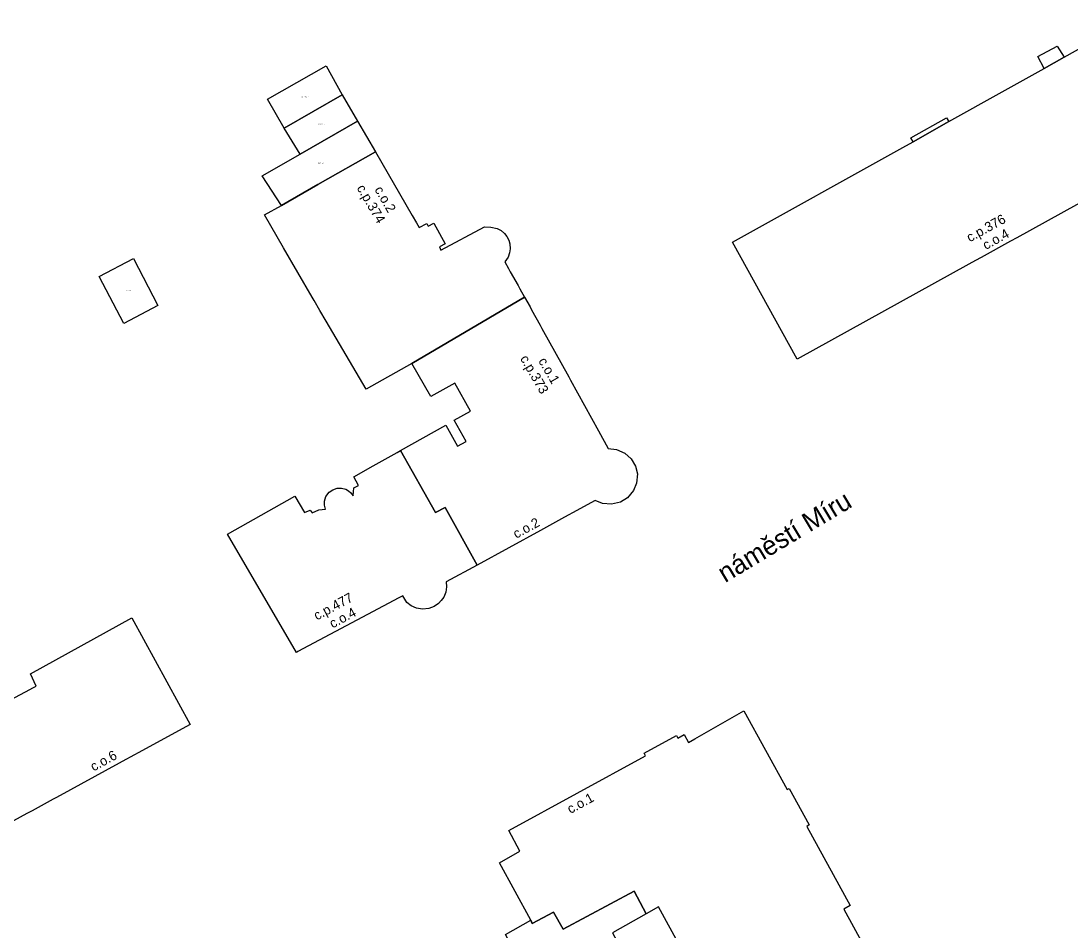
# Model space of a CAD drawing. Extents: x -600391 to -599491, y -1160176 to -1159402.
# Drawn here: x -600144.5 to -600035.1, y -1159820.9 to -1159726.1 of the extents above; entities that cross this region are included whole.
import ezdxf

# ---------------------------------------------------------------- set-up
doc = ezdxf.new("R2010")
doc.units = 0
for name, color, linetype in [('Level 10', 7, 'Continuous'), ('Level 11', 7, 'Continuous'), ('Level 12', 7, 'Continuous'), ('Level 24', 7, 'Continuous'), ('Level 25', 7, 'Continuous'), ('Level 61', 7, 'Continuous'), ('Level 62', 7, 'Continuous')]:
    doc.layers.add(name, color=color, linetype=linetype)

msp = doc.modelspace()

# ---------------------------------------------------------------- linework, layer by layer
at = {"layer": 'Level 61'}
for points in [[(-600035.83, -1159729.89), (-600029.11, -1159726.12)], [(-600038.55, -1159729.81), (-600036.54, -1159728.74)], [(-600036.54, -1159728.74), (-600035.83, -1159729.89)], [(-600037.91, -1159731.05), (-600038.55, -1159729.81)], [(-600035.83, -1159729.89), (-600037.91, -1159731.05)], [(-600037.91, -1159731.05), (-600035.83, -1159729.89)], [(-600118.8, -1159734.26), (-600112.68, -1159730.8)], [(-600112.68, -1159730.8), (-600111.01, -1159733.8)], [(-600042.29, -1159733.51), (-600037.91, -1159731.05)], [(-600117.04, -1159737.28), (-600118.8, -1159734.26)], [(-600111.01, -1159733.8), (-600117.04, -1159737.28)], [(-600117.04, -1159737.28), (-600111.01, -1159733.8)], [(-600111.01, -1159733.8), (-600109.42, -1159736.56)], [(-600047.82, -1159736.59), (-600042.29, -1159733.51)], [(-600051.77, -1159738.28), (-600048.07, -1159736.2)], [(-600048.07, -1159736.2), (-600047.82, -1159736.59)], [(-600115.4, -1159739.99), (-600117.04, -1159737.28)], [(-600115.4, -1159739.99), (-600109.42, -1159736.56)], [(-600109.42, -1159736.56), (-600115.4, -1159739.99)], [(-600109.42, -1159736.56), (-600107.55, -1159739.76)], [(-600047.82, -1159736.59), (-600051.53, -1159738.69)], [(-600051.53, -1159738.69), (-600047.82, -1159736.59)], [(-600052.61, -1159739.29), (-600051.53, -1159738.69)], [(-600051.53, -1159738.69), (-600051.77, -1159738.28)], [(-600022.11, -1159738.38), (-600040.75, -1159748.71)], [(-600113.55, -1159743.15), (-600107.55, -1159739.76)], [(-600107.55, -1159739.76), (-600113.55, -1159743.15)], [(-600107.55, -1159739.76), (-600103.72, -1159746.38)], [(-600070.35, -1159749.14), (-600052.61, -1159739.29)], [(-600119.33, -1159742.25), (-600115.4, -1159739.99)], [(-600117.35, -1159745.33), (-600119.33, -1159742.25)], [(-600117.35, -1159745.33), (-600113.55, -1159743.15)], [(-600113.55, -1159743.15), (-600117.35, -1159745.33)], [(-600119.11, -1159746.31), (-600117.35, -1159745.33)], [(-600117.14, -1159749.73), (-600119.11, -1159746.31)], [(-600103.72, -1159746.38), (-600103.73, -1159746.38)], [(-600103.73, -1159746.38), (-600103.28, -1159747.14)], [(-600103.28, -1159747.14), (-600102.99, -1159747.64)], [(-600102.99, -1159747.64), (-600102.21, -1159747.22)], [(-600102.21, -1159747.22), (-600102.05, -1159747.48)], [(-600102.05, -1159747.48), (-600101.47, -1159747.19)], [(-600101.47, -1159747.19), (-600100.27, -1159749.31)], [(-600100.73, -1159749.99), (-600096.19, -1159747.56)], [(-600096.19, -1159747.56), (-600095.53, -1159747.59)], [(-600095.53, -1159747.59), (-600094.88, -1159747.72)], [(-600094.88, -1159747.72), (-600094.47, -1159747.94)], [(-600094.47, -1159747.94), (-600094.11, -1159748.24)], [(-600094.11, -1159748.24), (-600093.87, -1159748.55)], [(-600093.87, -1159748.55), (-600093.66, -1159748.94)], [(-600100.27, -1159749.31), (-600100.89, -1159749.64)], [(-600100.89, -1159749.64), (-600100.73, -1159749.99)], [(-600093.66, -1159748.94), (-600093.54, -1159749.34)], [(-600093.54, -1159749.34), (-600093.52, -1159749.84)], [(-600063.64, -1159761.34), (-600070.35, -1159749.14)], [(-600041.39, -1159749.06), (-600044.45, -1159750.75)], [(-600040.75, -1159748.71), (-600041.39, -1159749.06)], [(-600114.14, -1159754.88), (-600117.14, -1159749.73)], [(-600093.74, -1159750.73), (-600094.08, -1159751.21)], [(-600093.57, -1159750.27), (-600093.74, -1159750.73)], [(-600093.52, -1159749.84), (-600093.57, -1159750.27)], [(-600044.45, -1159750.75), (-600045.04, -1159751.07)], [(-600136.31, -1159752.74), (-600132.76, -1159750.87)], [(-600132.76, -1159750.87), (-600130.2, -1159755.74)], [(-600094.08, -1159751.21), (-600093.7, -1159751.88)], [(-600045.74, -1159751.46), (-600063.64, -1159761.34)], [(-600045.04, -1159751.07), (-600045.74, -1159751.46)], [(-600133.75, -1159757.61), (-600136.31, -1159752.74)], [(-600093.7, -1159751.88), (-600093.5, -1159752.24)], [(-600093.5, -1159752.24), (-600092.7, -1159753.66)], [(-600092.7, -1159753.66), (-600092.5, -1159754.02)], [(-600092.5, -1159754.02), (-600092.01, -1159754.89)], [(-600113.94, -1159755.23), (-600114.14, -1159754.88)], [(-600103.75, -1159761.78), (-600092.01, -1159754.89)], [(-600092.01, -1159754.89), (-600103.75, -1159761.78)], [(-600092.01, -1159754.89), (-600091.45, -1159755.89)], [(-600130.2, -1159755.74), (-600133.75, -1159757.61)], [(-600113.33, -1159756.26), (-600113.94, -1159755.23)], [(-600091.45, -1159755.89), (-600091.28, -1159756.21)], [(-600091.28, -1159756.21), (-600090.39, -1159757.81)], [(-600112.67, -1159757.39), (-600113.33, -1159756.26)], [(-600108.53, -1159764.45), (-600112.67, -1159757.39)], [(-600090.39, -1159757.81), (-600090.22, -1159758.13)], [(-600090.22, -1159758.13), (-600087.41, -1159763.19)], [(-600103.75, -1159761.78), (-600108.53, -1159764.45)], [(-600101.78, -1159765.24), (-600103.75, -1159761.78)], [(-600099.27, -1159763.84), (-600101.78, -1159765.24)], [(-600097.66, -1159766.74), (-600099.27, -1159763.84)], [(-600087.41, -1159763.19), (-600087.23, -1159763.51)], [(-600087.23, -1159763.51), (-600084.3, -1159768.79)], [(-600099.36, -1159767.69), (-600097.66, -1159766.74)], [(-600104.93, -1159770.86), (-600100.22, -1159768.22)], [(-600100.22, -1159768.22), (-600099, -1159770.4)], [(-600098.11, -1159769.92), (-600099.36, -1159767.69)], [(-600084.3, -1159768.79), (-600083.31, -1159770.65)], [(-600099, -1159770.4), (-600098.11, -1159769.92)], [(-600107.78, -1159772.46), (-600105.3, -1159771.07)], [(-600105.3, -1159771.07), (-600104.93, -1159770.86)], [(-600101.3, -1159777.32), (-600104.93, -1159770.86)], [(-600104.93, -1159770.86), (-600101.3, -1159777.32)], [(-600083.31, -1159770.65), (-600082.43, -1159770.75)], [(-600082.43, -1159770.75), (-600081.59, -1159771.11)], [(-600081.59, -1159771.11), (-600080.91, -1159771.73)], [(-600109.79, -1159773.59), (-600107.78, -1159772.46)], [(-600080.91, -1159771.73), (-600080.46, -1159772.49)], [(-600080.46, -1159772.49), (-600080.27, -1159773.28)], [(-600109.32, -1159774.48), (-600109.79, -1159773.59)], [(-600080.27, -1159773.28), (-600080.35, -1159774.26)], [(-600111.99, -1159774.93), (-600111.52, -1159774.78)], [(-600111.52, -1159774.78), (-600111.07, -1159774.77)], [(-600111.07, -1159774.77), (-600110.65, -1159774.89)], [(-600109.88, -1159775.58), (-600109.79, -1159774.73)], [(-600109.79, -1159774.73), (-600109.32, -1159774.48)], [(-600080.35, -1159774.26), (-600080.68, -1159775.03)], [(-600122.96, -1159779.58), (-600115.94, -1159775.62)], [(-600115.94, -1159775.62), (-600114.95, -1159777.32)], [(-600112.86, -1159776.12), (-600112.7, -1159775.64)], [(-600112.7, -1159775.64), (-600112.37, -1159775.19)], [(-600112.37, -1159775.19), (-600111.99, -1159774.93)], [(-600110.65, -1159774.89), (-600110.36, -1159775.05)], [(-600110.36, -1159775.05), (-600110.1, -1159775.27)], [(-600110.1, -1159775.27), (-600109.88, -1159775.58)], [(-600081.3, -1159775.78), (-600082.03, -1159776.22)], [(-600080.68, -1159775.03), (-600081.3, -1159775.78)], [(-600113.43, -1159777.02), (-600112.76, -1159776.95)], [(-600112.87, -1159776.55), (-600112.86, -1159776.12)], [(-600112.76, -1159776.95), (-600112.87, -1159776.55)], [(-600100.29, -1159776.8), (-600101.3, -1159777.32)], [(-600101.3, -1159777.32), (-600100.29, -1159776.8)], [(-600096.97, -1159782.79), (-600100.29, -1159776.8)], [(-600100.29, -1159776.8), (-600096.97, -1159782.79)], [(-600086.26, -1159776.92), (-600086.59, -1159777.1)], [(-600084.65, -1159776.05), (-600086.26, -1159776.92)], [(-600083.89, -1159776.37), (-600084.65, -1159776.05)], [(-600082.95, -1159776.45), (-600083.89, -1159776.37)], [(-600082.03, -1159776.22), (-600082.95, -1159776.45)], [(-600114.95, -1159777.32), (-600114.36, -1159777.07)], [(-600114.36, -1159777.07), (-600114.14, -1159777.33)], [(-600114.14, -1159777.33), (-600113.43, -1159777.02)], [(-600088.17, -1159777.97), (-600090.37, -1159779.18)], [(-600087.85, -1159777.8), (-600088.17, -1159777.97)], [(-600086.59, -1159777.1), (-600087.85, -1159777.8)], [(-600090.37, -1159779.18), (-600096.97, -1159782.79)], [(-600115.78, -1159791.88), (-600122.96, -1159779.58)], [(-600096.97, -1159782.79), (-600100.19, -1159784.51)], [(-600100.19, -1159784.51), (-600100.15, -1159785.05)], [(-600100.23, -1159785.62), (-600100.44, -1159786.11)], [(-600100.15, -1159785.05), (-600100.23, -1159785.62)], [(-600105.12, -1159786.19), (-600108.36, -1159787.92)], [(-600104.68, -1159785.97), (-600105.12, -1159786.19)], [(-600104.28, -1159786.67), (-600104.68, -1159785.97)], [(-600103.83, -1159787.03), (-600104.28, -1159786.67)], [(-600100.99, -1159786.8), (-600101.45, -1159787.1)], [(-600100.7, -1159786.48), (-600100.99, -1159786.8)], [(-600100.44, -1159786.11), (-600100.7, -1159786.48)], [(-600108.36, -1159787.92), (-600115.62, -1159791.79)], [(-600103.28, -1159787.27), (-600103.83, -1159787.03)], [(-600102.64, -1159787.39), (-600103.28, -1159787.27)], [(-600101.99, -1159787.31), (-600102.64, -1159787.39)], [(-600101.45, -1159787.1), (-600101.99, -1159787.31)], [(-600143.49, -1159794.1), (-600132.93, -1159788.26)], [(-600132.93, -1159788.26), (-600126.86, -1159799.38)], [(-600115.62, -1159791.79), (-600115.78, -1159791.88)], [(-600142.89, -1159795.39), (-600143.49, -1159794.1)], [(-600144.01, -1159795.98), (-600143.17, -1159795.54)], [(-600143.17, -1159795.54), (-600142.89, -1159795.39)], [(-600147.35, -1159797.74), (-600144.01, -1159795.98)], [(-600074.28, -1159800.89), (-600069.17, -1159797.96)], [(-600069.17, -1159797.96), (-600064.67, -1159806.15)], [(-600126.86, -1159799.38), (-600132.26, -1159802.33)], [(-600079.57, -1159802.37), (-600076.21, -1159800.53)], [(-600076.21, -1159800.53), (-600076.04, -1159800.81)], [(-600076.04, -1159800.81), (-600075.4, -1159800.44)], [(-600075.4, -1159800.44), (-600074.93, -1159801.26)], [(-600074.93, -1159801.26), (-600074.28, -1159800.89)], [(-600133.92, -1159803.24), (-600134.24, -1159803.41)], [(-600132.65, -1159802.54), (-600133.92, -1159803.24)], [(-600132.26, -1159802.33), (-600132.65, -1159802.54)], [(-600093.64, -1159810.41), (-600079.43, -1159802.66)], [(-600079.43, -1159802.66), (-600079.57, -1159802.37)], [(-600134.24, -1159803.41), (-600140.76, -1159806.97)], [(-600064.67, -1159806.15), (-600064.47, -1159806.04)], [(-600064.47, -1159806.04), (-600062.36, -1159809.84)], [(-600141.11, -1159807.17), (-600143.3, -1159808.36)], [(-600140.76, -1159806.97), (-600141.11, -1159807.17)], [(-600143.85, -1159808.66), (-600154.94, -1159814.73)], [(-600143.59, -1159808.52), (-600143.85, -1159808.66)], [(-600143.3, -1159808.36), (-600143.59, -1159808.52)], [(-600092.5, -1159812.57), (-600093.64, -1159810.41)], [(-600062.36, -1159809.84), (-600062.62, -1159810)], [(-600062.62, -1159810), (-600058.11, -1159818.23)], [(-600094.64, -1159813.78), (-600092.5, -1159812.57)], [(-600091.37, -1159819.77), (-600094.64, -1159813.78)], [(-600080.6, -1159816.74), (-600087.98, -1159820.71)], [(-600087.98, -1159820.71), (-600080.6, -1159816.74)], [(-600079.35, -1159819.1), (-600080.6, -1159816.74)], [(-600080.6, -1159816.74), (-600079.35, -1159819.1)], [(-600078.08, -1159818.36), (-600079.35, -1159819.1)], [(-600063.12, -1159845.77), (-600078.08, -1159818.36)], [(-600058.11, -1159818.23), (-600058.78, -1159818.63)], [(-600089, -1159818.94), (-600091.21, -1159820.1)], [(-600091.21, -1159820.1), (-600089, -1159818.94)], [(-600087.98, -1159820.71), (-600089, -1159818.94)], [(-600089, -1159818.94), (-600087.98, -1159820.71)], [(-600079.35, -1159819.1), (-600082.86, -1159821.07)], [(-600058.78, -1159818.63), (-600048.7, -1159837.01)], [(-600094.02, -1159821.24), (-600091.37, -1159819.77)], [(-600091.21, -1159820.1), (-600091.37, -1159819.77)], [(-600091.37, -1159819.77), (-600091.21, -1159820.1)]]:
    msp.add_lwpolyline(points, dxfattribs=at)
at = {"layer": 'Level 62'}
for points in [[(-600029.11, -1159726.12), (-600023.56, -1159735.86), (-600022.96, -1159736.85), (-600022.79, -1159737.15), (-600022.11, -1159738.38), (-600040.75, -1159748.71), (-600041.39, -1159749.06), (-600044.45, -1159750.75), (-600045.04, -1159751.07), (-600045.74, -1159751.46), (-600063.64, -1159761.34), (-600070.35, -1159749.14), (-600052.61, -1159739.29), (-600051.53, -1159738.69), (-600047.82, -1159736.59), (-600042.29, -1159733.51), (-600037.91, -1159731.05), (-600035.83, -1159729.89), (-600029.11, -1159726.12)], [(-600038.55, -1159729.81), (-600036.54, -1159728.74), (-600035.83, -1159729.89), (-600037.91, -1159731.05), (-600038.55, -1159729.81)], [(-600111.01, -1159733.8), (-600117.04, -1159737.28), (-600118.8, -1159734.26), (-600112.68, -1159730.8), (-600111.01, -1159733.8)], [(-600111.01, -1159733.8), (-600109.42, -1159736.56), (-600115.4, -1159739.99), (-600117.04, -1159737.28), (-600111.01, -1159733.8)], [(-600047.82, -1159736.59), (-600051.53, -1159738.69), (-600051.77, -1159738.28), (-600048.07, -1159736.2), (-600047.82, -1159736.59)], [(-600117.35, -1159745.33), (-600119.33, -1159742.25), (-600115.4, -1159739.99), (-600109.42, -1159736.56), (-600107.55, -1159739.76), (-600113.55, -1159743.15), (-600117.35, -1159745.33)], [(-600107.55, -1159739.76), (-600103.72, -1159746.38), (-600103.73, -1159746.38), (-600103.28, -1159747.14), (-600102.99, -1159747.64), (-600102.21, -1159747.22), (-600102.05, -1159747.48), (-600101.47, -1159747.19), (-600100.27, -1159749.31), (-600100.89, -1159749.64), (-600100.73, -1159749.99), (-600096.19, -1159747.56), (-600095.53, -1159747.59), (-600094.88, -1159747.72), (-600094.47, -1159747.94), (-600094.11, -1159748.24), (-600093.87, -1159748.55), (-600093.66, -1159748.94), (-600093.54, -1159749.34), (-600093.52, -1159749.84), (-600093.57, -1159750.27), (-600093.74, -1159750.73), (-600094.08, -1159751.21), (-600093.7, -1159751.88), (-600093.5, -1159752.24), (-600092.7, -1159753.66), (-600092.5, -1159754.02), (-600092.01, -1159754.89), (-600103.75, -1159761.78), (-600108.53, -1159764.45), (-600112.67, -1159757.39), (-600113.33, -1159756.26), (-600113.94, -1159755.23), (-600114.14, -1159754.88), (-600117.14, -1159749.73), (-600119.11, -1159746.31), (-600117.35, -1159745.33), (-600113.55, -1159743.15), (-600107.55, -1159739.76)], [(-600136.31, -1159752.74), (-600132.76, -1159750.87), (-600130.2, -1159755.74), (-600133.75, -1159757.61), (-600136.31, -1159752.74)], [(-600086.26, -1159776.92), (-600086.59, -1159777.1), (-600087.85, -1159777.8), (-600088.17, -1159777.97), (-600090.37, -1159779.18), (-600096.97, -1159782.79), (-600100.29, -1159776.8), (-600101.3, -1159777.32), (-600104.93, -1159770.86), (-600100.22, -1159768.22), (-600099, -1159770.4), (-600098.11, -1159769.92), (-600099.36, -1159767.69), (-600097.66, -1159766.74), (-600099.27, -1159763.84), (-600101.78, -1159765.24), (-600103.75, -1159761.78), (-600092.01, -1159754.89), (-600091.45, -1159755.89), (-600091.28, -1159756.21), (-600090.39, -1159757.81), (-600090.22, -1159758.13), (-600087.41, -1159763.19), (-600087.23, -1159763.51), (-600084.3, -1159768.79), (-600083.31, -1159770.65), (-600082.43, -1159770.75), (-600081.59, -1159771.11), (-600080.91, -1159771.73), (-600080.46, -1159772.49), (-600080.27, -1159773.28), (-600080.35, -1159774.26), (-600080.68, -1159775.03), (-600081.3, -1159775.78), (-600082.03, -1159776.22), (-600082.95, -1159776.45), (-600083.89, -1159776.37), (-600084.65, -1159776.05), (-600086.26, -1159776.92)], [(-600104.93, -1159770.86), (-600101.3, -1159777.32), (-600100.29, -1159776.8), (-600096.97, -1159782.79), (-600100.19, -1159784.51), (-600100.15, -1159785.05), (-600100.23, -1159785.62), (-600100.44, -1159786.11), (-600100.7, -1159786.48), (-600100.99, -1159786.8), (-600101.45, -1159787.1), (-600101.99, -1159787.31), (-600102.64, -1159787.39), (-600103.28, -1159787.27), (-600103.83, -1159787.03), (-600104.28, -1159786.67), (-600104.68, -1159785.97), (-600105.12, -1159786.19), (-600108.36, -1159787.92), (-600115.62, -1159791.79), (-600115.78, -1159791.88), (-600122.96, -1159779.58), (-600115.94, -1159775.62), (-600114.95, -1159777.32), (-600114.36, -1159777.07), (-600114.14, -1159777.33), (-600113.43, -1159777.02), (-600112.76, -1159776.95), (-600112.87, -1159776.55), (-600112.86, -1159776.12), (-600112.7, -1159775.64), (-600112.37, -1159775.19), (-600111.99, -1159774.93), (-600111.52, -1159774.78), (-600111.07, -1159774.77), (-600110.65, -1159774.89), (-600110.36, -1159775.05), (-600110.1, -1159775.27), (-600109.88, -1159775.58), (-600109.79, -1159774.73), (-600109.32, -1159774.48), (-600109.79, -1159773.59), (-600107.78, -1159772.46), (-600105.3, -1159771.07), (-600104.93, -1159770.86)], [(-600143.49, -1159794.1), (-600132.93, -1159788.26), (-600126.86, -1159799.38), (-600132.26, -1159802.33), (-600132.65, -1159802.54), (-600133.92, -1159803.24), (-600134.24, -1159803.41), (-600140.76, -1159806.97), (-600141.11, -1159807.17), (-600143.3, -1159808.36), (-600143.59, -1159808.52), (-600143.85, -1159808.66), (-600154.94, -1159814.73), (-600157.7, -1159809.01), (-600156.72, -1159808.45), (-600162.28, -1159796.91), (-600150.75, -1159791.1), (-600147.35, -1159797.74), (-600144.01, -1159795.98), (-600143.17, -1159795.54), (-600142.89, -1159795.39), (-600143.49, -1159794.1)], [(-600091.37, -1159819.77), (-600094.64, -1159813.78), (-600092.5, -1159812.57), (-600093.64, -1159810.41), (-600079.43, -1159802.66), (-600079.57, -1159802.37), (-600076.21, -1159800.53), (-600076.04, -1159800.81), (-600075.4, -1159800.44), (-600074.93, -1159801.26), (-600074.28, -1159800.89), (-600069.17, -1159797.96), (-600064.67, -1159806.15), (-600064.47, -1159806.04), (-600062.36, -1159809.84), (-600062.62, -1159810), (-600058.11, -1159818.23), (-600058.78, -1159818.63), (-600048.7, -1159837.01)], [(-600079.35, -1159819.1), (-600082.86, -1159821.07), (-600080.07, -1159826.22), (-600078.2, -1159829.67), (-600084.15, -1159832.9), (-600086.85, -1159834.36), (-600088.71, -1159830.95), (-600094.02, -1159821.24), (-600091.37, -1159819.77), (-600091.21, -1159820.1), (-600089, -1159818.94), (-600087.98, -1159820.71), (-600080.6, -1159816.74), (-600079.35, -1159819.1)], [(-600063.12, -1159845.77), (-600078.08, -1159818.36), (-600079.35, -1159819.1), (-600080.6, -1159816.74), (-600087.98, -1159820.71), (-600089, -1159818.94), (-600091.21, -1159820.1), (-600091.37, -1159819.77)]]:
    msp.add_lwpolyline(points, dxfattribs=at)

# ---------------------------------------------------------------- texts
at = {"layer": 'Level 10'}
for s, rotation, p in [('c.o.2', 300.1855, (-600107.68, -1159743.68)), ('c.o.4', 28.9333, (-600043.97, -1159749.98)), ('c.o.1', 300.1649, (-600090.62, -1159761.52)), ('c.o.2', 28.7101, (-600092.88, -1159780.05)), ('c.o.4', 28.1335, (-600112.01, -1159789.39)), ('c.o.6', 28.8537, (-600136.9, -1159804.29)), ('c.o.1', 28.6077, (-600087.24, -1159808.71))]:
    msp.add_text(s, height=1, rotation=rotation, dxfattribs=at).set_placement(p)
at = {"layer": 'Level 11'}
msp.add_text('náměstí Míru', height=2, rotation=30.9418, dxfattribs=at).set_placement((-600071.14, -1159784.67))
at = {"layer": 'Level 12'}
for s, rotation, p in [('c.p.374', 300.1855, (-600109.53, -1159743.51)), ('c.p.376', 28.9333, (-600045.64, -1159749.18)), ('c.p.373', 300.1649, (-600092.52, -1159761.27)), ('c.p.477', 28.1335, (-600113.65, -1159788.56))]:
    msp.add_text(s, height=1, rotation=rotation, dxfattribs=at).set_placement(p)
at = {"layer": 'Level 24'}
msp.add_text('c.z.332', height=0.1, dxfattribs=at).set_placement((-600133.49, -1159754.25))
at = {"layer": 'Level 25'}
for s, p in [('c.pp.374_C', (-600115.23, -1159734.08)), ('c.pp.374_B', (-600113.49, -1159736.9)), ('c.pp.374_A', (-600113.65, -1159740.94))]:
    msp.add_text(s, height=0.1, dxfattribs=at).set_placement(p)

doc.saveas('drawing.dxf')
